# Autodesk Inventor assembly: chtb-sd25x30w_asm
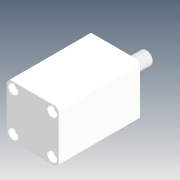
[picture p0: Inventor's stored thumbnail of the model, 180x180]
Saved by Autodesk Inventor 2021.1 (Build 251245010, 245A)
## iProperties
Company: Microsoft
Created: 2018-05
Part Number: chtb-sd25x30w_asm
Description: STEP AP214
Document SubType Name: Assembly
Designer: user
Title: chtb-sd25x30w_asm.STEP
Author: Windows
Revision Number: ÈÎºÎ
Sending System: SolidWorks 2015
Preprocessor: SwSTEP 2.0
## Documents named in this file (4)
- D:\Vault_2016\Projekty\Clamptek\Hydraulic\CHTB\CHTB-25\Inventor\chtb-sd25x30w\chtb-sd25x30w_asm.iam
- D:\Vault_2016\Projekty\Clamptek\Hydraulic\CHTB\CHTB-25\Inventor\chtb-sd25x30w\CHTB-25QG.ipt
- D:\Vault_2016\Projekty\Clamptek\Hydraulic\CHTB\CHTB-25\Inventor\chtb-sd25x30w\CHTB-SD25X30NBT.ipt
- D:\Vault_2016\Projekty\Clamptek\Hydraulic\CHTB\CHTB-25\Inventor\chtb-sd25x30w\CHTB-SD25X30WHSG.ipt
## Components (3 placed, 3 different names)
1. CHTB-25QG_1
2. CHTB-SD25X30NBT_2
3. CHTB-SD25X30WHSG_3
